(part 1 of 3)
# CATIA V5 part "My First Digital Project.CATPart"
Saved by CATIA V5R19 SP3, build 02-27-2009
Part number: My First Digital Project
Publications: "ElevationGridHeightReference", "Building Levels_ElevationOfRefHeight", "Level 1", "Roof Peak", "A", "B", "C", "D", "E", "F", "G", "H", "I", "1", "2", "3", "4", "5", "6", "7", "8", "9", "A-1", "A-2", "A-3", "A-4", "A-5", "A-6", "A-7", "A-8", "A-9", "B-1", "B-2", "B-3", "B-4", "B-5", "B-6", "B-7", "B-8", "B-9", "C-1", "C-2", "C-3", "C-4", "C-5", "C-6", "C-7", "C-8", "C-9", "D-1", "D-2", "D-3", "D-4", "D-5", "D-6", "D-7", "D-8", "D-9", "E-1", "E-2", "E-3", "E-4", "E-5", "E-6", "E-7", "E-8", "E-9", "F-1", "F-2", "F-3", "F-4", "F-5", "F-6", "F-7", "F-8", "F-9", "G-1", "G-2", "G-3", "G-4", "G-5", "G-6", "G-7", "G-8", "G-9", "H-1", "H-2", "H-3", "H-4", "H-5", "H-6", "H-7", "H-8", "H-9", "I-1", "I-2", "I-3", "I-4", "I-5", "I-6", "I-7", "I-8", "I-9"
Material "Brushed metal 2": density 7860 kg/m3, Young's modulus 2e+11 Pa, Poisson ratio 0.266
Material "Brushed metal 2": density 7860 kg/m3, Young's modulus 2e+11 Pa, Poisson ratio 0.266
Material "Brushed metal 2": density 7860 kg/m3, Young's modulus 2e+11 Pa, Poisson ratio 0.266
Material "Brushed metal 2": density 7860 kg/m3, Young's modulus 2e+11 Pa, Poisson ratio 0.266
Material "Brushed metal 2": density 7860 kg/m3, Young's modulus 2e+11 Pa, Poisson ratio 0.266
Material "Brushed metal 2": density 7860 kg/m3, Young's modulus 2e+11 Pa, Poisson ratio 0.266
Material "Brushed metal 2": density 7860 kg/m3, Young's modulus 2e+11 Pa, Poisson ratio 0.266
Material "Brushed metal 2": density 7860 kg/m3, Young's modulus 2e+11 Pa, Poisson ratio 0.266
Material "Brushed metal 2": density 7860 kg/m3, Young's modulus 2e+11 Pa, Poisson ratio 0.266
Material "Brushed metal 2": density 7860 kg/m3, Young's modulus 2e+11 Pa, Poisson ratio 0.266
Material "Brushed metal 2": density 7860 kg/m3, Young's modulus 2e+11 Pa, Poisson ratio 0.266
Material "Brushed metal 2": density 7860 kg/m3, Young's modulus 2e+11 Pa, Poisson ratio 0.266
Material "Brushed metal 2": density 7860 kg/m3, Young's modulus 2e+11 Pa, Poisson ratio 0.266
Material "Brushed metal 2": density 7860 kg/m3, Young's modulus 2e+11 Pa, Poisson ratio 0.266
Material "Brushed metal 2": density 7860 kg/m3, Young's modulus 2e+11 Pa, Poisson ratio 0.266
Material "Brushed metal 2": density 7860 kg/m3, Young's modulus 2e+11 Pa, Poisson ratio 0.266
Material "Brushed metal 2": density 7860 kg/m3, Young's modulus 2e+11 Pa, Poisson ratio 0.266
Material "Brushed metal 2": density 7860 kg/m3, Young's modulus 2e+11 Pa, Poisson ratio 0.266
Material "Wall of Castle": density 2770 kg/m3, Young's modulus 6e+10 Pa, Poisson ratio 0.27, thermal expansion 7e-06 1/K
Material "Wall of Castle": density 2770 kg/m3, Young's modulus 6e+10 Pa, Poisson ratio 0.27, thermal expansion 7e-06 1/K
Material "Wall of Castle": density 2770 kg/m3, Young's modulus 6e+10 Pa, Poisson ratio 0.27, thermal expansion 7e-06 1/K
Material "Wall of Castle": density 2770 kg/m3, Young's modulus 6e+10 Pa, Poisson ratio 0.27, thermal expansion 7e-06 1/K
Material "Wall of Castle": density 2770 kg/m3, Young's modulus 6e+10 Pa, Poisson ratio 0.27, thermal expansion 7e-06 1/K
Material "Wall of Castle": density 2770 kg/m3, Young's modulus 6e+10 Pa, Poisson ratio 0.27, thermal expansion 7e-06 1/K
Material "Wall of Castle": density 2770 kg/m3, Young's modulus 6e+10 Pa, Poisson ratio 0.27, thermal expansion 7e-06 1/K
Material "Wall of Castle": density 2770 kg/m3, Young's modulus 6e+10 Pa, Poisson ratio 0.27, thermal expansion 7e-06 1/K
Material "Wall of Castle": density 2770 kg/m3, Young's modulus 6e+10 Pa, Poisson ratio 0.27, thermal expansion 7e-06 1/K
Material "Wall of Castle": density 2770 kg/m3, Young's modulus 6e+10 Pa, Poisson ratio 0.27, thermal expansion 7e-06 1/K
Material "Concrete": density 2320 kg/m3, Young's modulus 2.5e+10 Pa, Poisson ratio 0.3, thermal expansion 1e-05 1/K
Material "Steel": density 7860 kg/m3, Young's modulus 2e+11 Pa, Poisson ratio 0.266, thermal expansion 1.17e-05 1/K
Material "Steel": density 7860 kg/m3, Young's modulus 2e+11 Pa, Poisson ratio 0.266, thermal expansion 1.17e-05 1/K
Material "Steel": density 7860 kg/m3, Young's modulus 2e+11 Pa, Poisson ratio 0.266, thermal expansion 1.17e-05 1/K
Material "Steel": density 7860 kg/m3, Young's modulus 2e+11 Pa, Poisson ratio 0.266, thermal expansion 1.17e-05 1/K
Material "Steel": density 7860 kg/m3, Young's modulus 2e+11 Pa, Poisson ratio 0.266, thermal expansion 1.17e-05 1/K
Material "Steel": density 7860 kg/m3, Young's modulus 2e+11 Pa, Poisson ratio 0.266, thermal expansion 1.17e-05 1/K
Material "Steel": density 7860 kg/m3, Young's modulus 2e+11 Pa, Poisson ratio 0.266, thermal expansion 1.17e-05 1/K
Material "Steel": density 7860 kg/m3, Young's modulus 2e+11 Pa, Poisson ratio 0.266, thermal expansion 1.17e-05 1/K
Material "Ox B&W Stripes": density 2000 kg/m3
Bounding box of the stored display mesh (mm): x -2751.913 to 38639.977, y -3048 to 24319.59, z -304.8 to 7419.866
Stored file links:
  D:\Work\2009-03-18 GT Knowledge SVN\GT.KNOWLEDGE\Training\Work\2009-T02.GettingStarted\Models\My First Digital Project.CATPart
  D:\Work\2009-03-18 GT Knowledge SVN\GT.KNOWLEDGE\Training\Work\2009-T02.GettingStarted\Models\Starter Sketches.CATPart
  C:\Program Files\Gehry Technologies\Digital Project V1,R4\Project Standards\startup\Catalogs\LayerSets\Standard Wall Layer Sets Imperial\ResolvedParts\CMU_8___-Partition.CATPart
  C:\Program Files\Gehry Technologies\Digital Project V1,R4\Project Standards\startup\Catalogs\Doors\IFC\IFC Single Swing - Lining - Glass.CATPart
  C:\Program Files\Gehry Technologies\Digital Project V1,R4\Project Standards\startup\Catalogs\Windows\IFC\Single Panel - Symbolic.CATPart
  C:\Program Files\Gehry Technologies\Digital Project V1,R4\Project Standards\startup\Catalogs\Windows\IFC\IFC Single Panel.CATPart
  C:\Program Files\Gehry Technologies\Digital Project V1,R4\Project Standards\startup\Catalogs\Windows\IFC\IFC Triple Panel Vertical.CATPart
  C:\Program Files\Gehry Technologies\Digital Project V1,R4\Project Standards\startup\Catalogs\LayerSets\Standard Wall Layer Sets Imperial\ResolvedParts\CMU_12__-Structure_with_Surface.CATPart
  D:\Work\2009-03-18 GT Knowledge SVN\GT.KNOWLEDGE\Training\Work\2009-T02.GettingStarted\Models\My First Drawing Sheet Redux.CATDrawing
  D:\Work\2009-03-18 GT Knowledge SVN\GT.KNOWLEDGE\Training\Work\2009-T02.GettingStarted\Models\My First Drawing Sheet.CATDrawing
  C:\Program Files\Gehry Technologies\Digital Project V1,R4\Project Standards\startup\materials\Catalog.CATMaterial
  C:\Program Files\Gehry Technologies\Digital Project V1,R4\Project Standards\startup\materials\brushed_metal1.jpg
  C:\Program Files\Gehry Technologies\Digital Project V1,R4\Project Standards\startup\materials\brushed_metal2.jpg
  C:\Program Files\Gehry Technologies\Digital Project V1,R4\Project Standards\startup\materials\wall_of_castle.jpg
  C:\Program Files\Gehry Technologies\Digital Project V1,R4\Project Standards\startup\materials\concrete.jpg
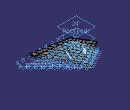
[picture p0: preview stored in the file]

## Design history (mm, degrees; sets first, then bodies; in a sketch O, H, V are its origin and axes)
GTCArcElevationGrid1 "Building Levels": ElevationOfRefHeight 0
GTCArcSlab1 "Slab"
GTCArcSlab2 "Slab"
GTCArcColumn1 "Column"
GTCArcColumn2 "Column"
GTCArcColumn3 "Column"
GTCArcColumn4 "Column"
GTCArcColumn5 "Column"
GTCArcColumn6 "Column"
GTCArcColumn7 "Column"
GTCArcColumn8 "Column"
GTCArcWall1 "Wall"
GTCArcWall2 "Wall"
GTCArcWall3 "Wall"
GTCArcWall4 "Wall"
GTCArcWall5 "Wall"
GTCArcWall6 "Wall"
GTCArcWall7 "Wall"
GTCArcWall8 "Wall"
GTCArcWall9 "Wall"
GTCArcWall10 "Wall"
GTCArcBeam1 "Beam"
GTCArcBeam2 "Beam"
GTCArcBeam3 "Beam"
GTCArcBeam4 "Beam"
GTCArcBeam5 "Beam"
GTCArcBeam6 "Beam"
GTCArcBeam7 "Beam"
GTCArcBeam8 "Beam"
GTCArcBeam9 "Beam"
GTCArcBeam10 "Beam"
GTCArcBeam11 "Beam"
GTCArcBeam12 "Beam"
GTCArcBeam13 "Beam"
GTCArcBeam14 "Beam"
GTCArcBeam15 "Beam"
GTCArcBeam16 "Beam"
GTCArcBeam17 "Beam"
GTCArcBeam18 "Beam"
GTCArcSectionCatalogRoot1 "Section Catalogs"
GTCArcPlanGrid1 "Grid East-West"
GTCArcPlanGrid2 "Grid North-South"
GTCArcIntersectionGrid1 "Grid Points"
GTCArcSheets1 "A&S Sheets"
Set1
  AxisSystem1: origin (0, 0, 0), X (1, 0, 0), Y (0, 1, 0), Z (0, 0, 1)
  Sketch1 on xy-plane, origin (0, 0, 0), H (1, 0, 0), V (0, 1, 0)
    point P1 (0, 14720.7096)
    line L1 (0, 14720.7096) -> (13368.4042, 22038.0431)
    line L2 (13368.4042, 22038.0431) -> (34424.4022, 0)
    line L3 (34424.4022, 0) -> (3944.4022, 0)
    line L4 (3944.4022, 0) -> (0, 14720.7096)
    point P3 (34424.4022, 0)
    construction line L5 (34424.4022, 0) -> (0, 14720.7096)
    angle L4 V = 15
    length L3 = 30480
    length L4 = 15240
    coincidence: P1 V, P3 H
    horizontal: L3 H
    symmetry: L3 L2 L5, L4 L1 L5
  Plane1: type Offset, RefPlane xy-plane, Offset 7315.2
  Line1: type PtDir, RefPoint sketch element, Direction xy-plane, Start 0, End 2438.4
  Line2: type PtDir, RefPoint sketch element, Direction xy-plane, Start 0, End 5486.4
  Line3: type PtDir, RefPoint sketch element, Direction xy-plane, Start 0, End 2438.4
  Line4: type PtDir, RefPoint sketch element, Direction xy-plane, Start 0, End 2438.4
  LineCorner1: Elements (vertex of Line1; vertex of Line2; vertex of Line3; vertex of Line4)
  Fill1: Boundary LineCorner1
  Sketch2 "Partitions" on xy-plane, origin (0, 0, 0), H (1, 0, 0), V (0, 1, 0)
    projected line E1 (34424.4022, 0) -> (3944.4022, 0) from sketch element
    projected line E2 (0, 14720.7096) -> (3944.4022, 0) from sketch element
    projected line E3 (0, 14720.7096) -> (13368.4042, 22038.0431) from sketch element
    projected line E4 (34424.4022, 0) -> (13368.4042, 22038.0431) from sketch element
    construction line L1 (0, 14720.7096) -> (34424.4022, 0)
    line L2 (8325.3671, 1828.8) -> (4962.35, 3266.9077)
    point P9 (4962.35, 3266.9077)
    line L3 (4962.35, 3266.9077) -> (4880.5472, 8987.1813)
    point P10 (4880.5472, 8987.1813)
    line L4 (4880.5472, 8987.1813) -> (7517.078, 15152.7126)
    point P11 (7517.078, 15152.7126)
    line L5 (7517.078, 15152.7126) -> (11709.5345, 19045.2091)
    point P12 (11709.5345, 19045.2091)
    line L6 (11709.5345, 19045.2091) -> (15072.5516, 17607.1014)
    point P13 (8325.3671, 1828.8)
    point P14 (15072.5516, 17607.1014)
    point P15 (6198.8126, 12069.9469)
    point P16 (13968.8059, 8084.3115)
    point P17 (13390.1652, 7011.1742)
    point P18 (12719.1739, 5993.2256)
    point P19 (11964.8857, 5035.3645)
    point P20 (14448.1752, 9205.3172)
    point P21 (14824.3558, 10365.0312)
    point P22 (15096.8362, 11553.3927)
    point P23 (15268.3289, 12760.4714)
    line L7 (2138.3258, 13806.3096) -> (5347.6898, 1828.8)
    line L8 (5347.6898, 1828.8) -> (30147.7506, 1828.8)
    line L9 (30147.7506, 1828.8) -> (13015.5317, 19760.0601)
    line L10 (13015.5317, 19760.0601) -> (2138.3258, 13806.3096)
    spline S1 through (8325.3671, 1828.8) (14221.2222, 8639.3699) (15072.5516, 17607.1014)
    construction line L11 (15072.5516, 17607.1014) -> (8325.3671, 1828.8)
    construction line L12 (11709.5345, 19045.2091) -> (4962.35, 3266.9077)
    construction spline S2 through (11709.5345, 19045.2091) (5813.6795, 12234.6392) (4962.35, 3266.9077)
    construction line L13 (13391.0431, 18326.1553) -> (6643.8586, 2547.8539)
    point P28 (13391.0431, 18326.1553)
    point P29 (6643.8586, 2547.8539)
    point P30 (8325.3671, 1828.8)
    point P31 (14221.2222, 8639.3699)
    point P32 (15072.5516, 17607.1014)
    point P33 (11709.5345, 19045.2091)
    point P34 (5813.6795, 12234.6392)
    point P35 (4962.35, 3266.9077)
    length L4 = 6705.6
    distance L1 P16 = 609.6
    distance P16 P17 = 1219.2
    distance P17 P18 = 1219.2
    distance P18 P19 = 1219.2
    length L6 = 3657.6
    distance P31 L11 = 2743.2
    distance L12 P34 = 2743.2
    distance L8 E1 = 1828.8
    distance L7 E2 = 1828.8
    parallelism: L6 L1
    midpoint: P15 L4, P28 L6, P29 L2
    coincidence: P16 S1, P17 S1, P18 S1, P19 S1, L8 P13, L7 P9, P12 L10, L9 P14, P30 P13, P31 L1, P32 P14, P33 P12, P34 L1, P35 P9, P15 L1, P11 S2, P10 S2
    symmetry: P16 P20 L1, P17 P21 L1, P18 P22 L1, P19 P23 L1, L2 L6 L1, L7 L10 L1, L8 L9 L1
  Sketch3 "Grid" on xy-plane, origin (0, 0, 0), H (1, 0, 0), V (0, 1, 0)
    projected line E1 (34424.4022, 0) -> (3944.4022, 0) from sketch element
    projected line E2 (34424.4022, 0) -> (13368.4042, 22038.0431) from sketch element
    point P3 (34424.4022, 0)
    projected line E3 (0, 14720.7096) -> (13368.4042, 22038.0431) from sketch element
    point P5 (0, 14720.7096)
    point P6 (13368.4042, 22038.0431)
    projected line E4 (0, 14720.7096) -> (3944.4022, 0) from sketch element
    point P7 (0, 14720.7096)
    point P8 (3944.4022, 0)
    point P9 (493.0503, 12880.6209)
    point P10 (986.1006, 11040.5322)
    point P11 (1479.1508, 9200.4435)
    point P12 (1972.2011, 7360.3548)
    point P13 (2465.2514, 5520.2661)
    point P14 (2958.3017, 3680.1774)
    point P15 (3451.352, 1840.0887)
    point P16 (31792.4025, 2754.7554)
    point P17 (29160.4027, 5509.5108)
    point P18 (26528.403, 8264.2662)
    point P19 (23896.4032, 11019.0216)
    point P20 (21264.4034, 13773.777)
    point P21 (18632.4037, 16528.5323)
    point P22 (16000.4039, 19283.2877)
    point P23 (23896.4032, 11019.0216)
    construction line L1 (34424.4022, 0) -> (0, 14720.7096)
    offset line E5 (36628.2066, 2105.5998) -> (15572.2085, 24143.6429) from sketch element
    offset line E6 (38639.978, 0) -> (15572.2085, 24143.6429) from sketch element
    line L2 (35881.8776, 2886.7373) -> (322.8841, 1739.1219)
    point P26 (35881.8776, 2886.7373)
    line L3 (33112.3623, 5785.4219) -> (-139.2731, 3463.9162)
    point P27 (33112.3623, 5785.4219)
    line L4 (30329.8087, 8697.7529) -> (-596.7117, 5171.1004)
    point P28 (30329.8087, 8697.7529)
    line L5 (27532.2702, 11625.7677) -> (-1048.2612, 6856.3061)
    point P29 (27532.2702, 11625.7677)
    line L6 (24717.3924, 14571.9305) -> (-1492.3291, 8513.5901)
    point P30 (24717.3924, 14571.9305)
    line L7 (21882.3005, 17539.2502) -> (-1926.6918, 10134.6538)
    point P31 (21882.3005, 17539.2502)
    line L8 (19023.4469, 20531.4399) -> (-2348.1478, 11707.5487)
    point P32 (19023.4469, 20531.4399)
    point P33 (-2348.1478, 11707.5487)
    reference offset line E7 (-2944.1419, 13931.8291) -> (1000.2603, -788.8804) from sketch element
    point P36 (-2348.1478, 11707.5487)
    point P37 (-1926.6918, 10134.6538)
    point P38 (-1492.3291, 8513.5901)
    point P39 (-1048.2612, 6856.3061)
    point P40 (-596.7117, 5171.1004)
    point P41 (-139.2731, 3463.9162)
    point P42 (322.8841, 1739.1219)
    point P43 (556.4821, 18500.0302)
    point P44 (8940.3063, -3048)
    line L9 (8940.3063, -3048) -> (556.4821, 18500.0302)
    point P45 (1984.8844, 19281.8809)
    point P46 (13078.6928, -3048)
    line L10 (13078.6928, -3048) -> (1984.8844, 19281.8809)
    point P47 (3457.0305, 20087.6752)
    point P48 (17182.6826, -3048)
    line L11 (17182.6826, -3048) -> (3457.0305, 20087.6752)
    point P49 (4962.0694, 20911.4737)
    point P50 (21257.4111, -3048)
    line L12 (21257.4111, -3048) -> (4962.0694, 20911.4737)
    point P51 (6492.4652, 21749.1516)
    point P52 (25307.0398, -3048)
    line L13 (25307.0398, -3048) -> (6492.4652, 21749.1516)
    point P53 (8042.8203, 22597.7544)
    point P54 (29334.9768, -3048)
    line L14 (29334.9768, -3048) -> (8042.8203, 22597.7544)
    point P55 (9609.1679, 23455.1109)
    point P56 (33344.0399, -3048)
    line L15 (33344.0399, -3048) -> (9609.1679, 23455.1109)
    line L16 (38639.978, 0) -> (788.8804, 0)
    point P57 (38639.978, 0)
    point P58 (788.8804, 0)
    line L17 (16136.4022, 23553.1353) -> (-2751.9132, 13214.4216)
    point P59 (-2751.9132, 13214.4216)
    point P60 (16136.4022, 23553.1353)
    point P61 (-811.9632, 17750.9976)
    point P62 (4761.1114, -3048)
    line L18 (4761.1114, -3048) -> (-811.9632, 17750.9976)
    point P63 (11188.5268, 24319.5892)
    point P64 (37336.5792, -3048)
    line L19 (37336.5792, -3048) -> (11188.5268, 24319.5892)
    distance P7 P9 = 1905 {= Sketch3.length(E4) /8}
    distance P9 P10 = 1905 {= Sketch3.distance(P7 P9)}
    distance P10 P11 = 1905 {= Sketch3.distance(P7 P9)}
    distance P11 P12 = 1905 {= Sketch3.distance(P7 P9)}
    distance P12 P13 = 1905 {= Sketch3.distance(P7 P9)}
    distance P13 P14 = 1905 {= Sketch3.distance(P7 P9)}
    distance P14 P15 = 1905 {= Sketch3.distance(P7 P9)}
    distance P3 P16 = 3810 {= Sketch3.length(E2) /8}
    distance P16 P17 = 3810 {= Sketch3.distance(P3 P16)}
    distance P17 P18 = 3810 {= Sketch3.distance(P3 P16)}
    distance P18 P19 = 3810 {= Sketch3.distance(P3 P16)}
    distance P19 P20 = 3810 {= Sketch3.distance(P3 P16)}
    distance P20 P21 = 3810 {= Sketch3.distance(P3 P16)}
    distance P21 P22 = 3810 {= Sketch3.distance(P3 P16)}
    length E4 = 15240 (reference)
    length E2 = 30480 (reference)
    coincidence: E4 P9, E4 P10, E4 P11, E4 P12, E4 P13, E4 P14, E4 P15, E2 P16, E2 P17, E2 P18, E2 P19, E2 P20, E2 P21, E2 P22, P23 E2, P26 E5, P15 L2, P16 L2, P27 E5, P14 L3, P17 L3, P28 E5, P18 L4, P13 L4, P29 E5, P30 E5, P31 E5, P32 E5, L8 P9, P19 L5, P12 L5, P20 L6, P11 L6, P21 L7, P10 L7, P22 L8, E7 P36, E7 P37, E7 P38, E7 P39, E7 P40, E7 P41, E7 P42, P3 L16, P8 L16, E7 P58, P6 L17, P5 L17, E7 P59, E5 P60
    symmetry: P36 P43 L1, P32 P44 L1, L8 L9 L1, P37 P45 L1, P31 P46 L1, L7 L10 L1, P38 P47 L1, P30 P48 L1, L6 L11 L1, P39 P49 L1, P29 P50 L1, L5 L12 L1, P40 P51 L1, P28 P52 L1, L4 L13 L1, P41 P53 L1, P27 P54 L1, L3 L14 L1, P42 P55 L1, P26 P56 L1, L2 L15 L1, P59 P61 L1, P60 P62 L1, L17 L18 L1, P58 P63 L1, P57 P64 L1, L16 L19 L1
    horizontal: L16 H
  Plane2: type 2Lines, Element1 {line type PtPt}, Element2 Z axis
Body1 (main body)
Body2 "Structural Solid Body", material "Ox B&W Stripes"
  GTCArcStrSlabSolidRes1 "Structural Solid": Perimeter 92819.0285, SurfaceArea 453.635, GrossVolume 23.0514
Body3 "Structural Solid Body", material "Concrete"
  GTCArcStrSlabSolidRes2 "Structural Solid": Perimeter 43729.3587, SurfaceArea 121.885, GrossVolume 37.1506
Set2 "Construction Geometry"
  Point1 "Construction Point 1": type OnCurve, Support sketch element
  Point2 "Construction Point 2": type OnCurve, Support sketch element
Set3 "Construction Geometry"
  Point3 "Construction Point 1": type OnCurve, Support sketch element
  Point4 "Construction Point 2": type OnCurve, Support sketch element
Set4 "Construction Geometry"
  Point5 "Construction Point 1": type OnCurve, Support sketch element
  Point6 "Construction Point 2": type OnCurve, Support sketch element
Set5 "Construction Geometry"
  Point7 "Construction Point 1": type OnCurve, Support sketch element
  Point8 "Construction Point 2": type OnCurve, Support sketch element
Set6 "Construction Geometry"
  Point9 "Construction Point 1": type OnCurve, Support sketch element
  Point10 "Construction Point 2": type OnCurve, Support sketch element
Set7 "Construction Geometry"
  Point11 "Construction Point 1": type OnCurve, Support sketch element
  Point12 "Construction Point 2": type OnCurve, Support sketch element
Body4 "Envelope Body", material "Wall of Castle"
  GTCArcWallEnvRes1 "Envelope": NominalLength 18040.4439, GrossFootPrintArea 3.66582, NetFootPrintArea 3.2528, GrossVolume 14.9783
Body5 "Envelope Body", material "Wall of Castle"
  GTCArcWallEnvRes2 "Envelope": NominalLength 3526.5012, GrossFootPrintArea 0.716585, NetFootPrintArea 0.716585, GrossVolume 2.39329
Body6 "Envelope Body", material "Wall of Castle"
  GTCArcWallEnvRes3 "Envelope": NominalLength 5772.1499, GrossFootPrintArea 1.1729, NetFootPrintArea 1.1729, GrossVolume 4.45137
Body7 "Envelope Body", material "Wall of Castle"
  GTCArcWallEnvRes4 "Envelope": NominalLength 6662.4603, GrossFootPrintArea 1.35381, NetFootPrintArea 1.35381, GrossVolume 5.80118
Body8 "Envelope Body", material "Wall of Castle"
  GTCArcWallEnvRes5 "Envelope": NominalLength 5494.3971, GrossFootPrintArea 1.11646, NetFootPrintArea 1.11646, GrossVolume 4.17586
Body9 "Envelope Body", material "Wall of Castle"
  GTCArcWallEnvRes6 "Envelope": NominalLength 3544.8468, GrossFootPrintArea 0.720313, NetFootPrintArea 0.720313, GrossVolume 2.4124
Body10 "Opening Volume Body"
  GTCArcGeoOpnVolume1 "Opening Volume"
Set8 "IFC Single Swing - Lining - Glass"
  Set9 "Construction Geometry"
    UdfFeature1 "Insertion Axis": UdfInputSpec1 {planeoffsetpt RefPlane Plane3}, UdfInputSpec2 Project1, UdfInputSpec3 Project2, UdfInputSpec4 {lineangle Support Plane4, Start 0, End 304.8, Angle 90}, UdfComponents Set12, UdfOutputs AxisSystem4
    AxisSystem2 "Insertion Axis Clone": origin (12134.1448, 5559.1105, 0), X (-0.6499, -0.76, 0), Y (0.76, -0.6499, 0), Z (0, 0, 1)
    AxisSystem3 "Panel Axis": origin (12257.6772, 5420.0475, 12.7), X (-0.6499, -0.76, 0), Y (0.76, -0.6499, 0), Z (0, 0, 1)
    UdfFeature2 "Middle": UdfInputSpec1 {pointcoord X 25.2984 {= `UdfFeature2.Inner Offset`}, Y 0, Z 0, RefAxis AxisSystem3}, UdfInputSpec2 {pointcoord X 482.6508 {= `UdfFeature2.Door Width` /2}, Y 0, Z 0, RefAxis AxisSystem3}, UdfInputSpec3 {pointcoord X 940.0032 {= `UdfFeature2.Door Width` -`UdfFeature2.Inner Offset`}, Y 0, Z 0, RefAxis AxisSystem3}, UdfComponents Set13, UdfOutputs Point14
  Set10 "Door Lining"
    Sketch4 "Opening Contour" on edge [XY plane of AxisSystem2 | ZX plane of AxisSystem2], origin (12134.1448, 5559.1105, 0), H (-0.6499, -0.76, 0), V (0, 0, 1)
      line L1 (0, 0) -> (0, 2476.5)
      line L2 (0, 2476.5) -> (1016.1016, 2476.5)
      line L3 (1016.1016, 2476.5) -> (1016.1016, 0)
      point P3 (1016.1016, 0)
      length L1 = 2476.5
      length L2 = 1016.1016
      vertical: L1 V, L3 V
      horizontal: L2 H
      coincidence: P3 H
    Body11 "Lining"
      Sketch5 on edge [XY plane of AxisSystem2 | ZX plane of AxisSystem2], origin (12134.1448, 5559.1105, 0), H (-0.6499, -0.76, 0), V (0.76, -0.6499, 0)
        point P1 (0, 203.315)
        line L1 (0, 203.315) -> (25.4, 203.315)
        line L2 (25.4, 203.315) -> (25.4, 0)
        line L3 (25.4, 0) -> (0, 0)
        line L4 (0, 0) -> (0, 203.315)
        distance H L1 = 203.315
        length L1 = 25.4
        length L4 = 203.315
        coincidence: P1 V
        horizontal: L1 H, L3 H
        vertical: L2 V, L4 V
      Rib1: profile Sketch5, centre curve Sketch4
    Body12 "Threshold"
      Sketch6 on edge [YZ plane of AxisSystem2 | XY plane of AxisSystem2], origin (12134.1448, 5559.1105, 0), H (0.76, -0.6499, 0), V (0, 0, 1)
        line L1 (0, 12.7) -> (203.315, 12.7)
        line L2 (203.315, 12.7) -> (203.315, 0)
        line L3 (203.315, 0) -> (0, 0)
        line L4 (0, 0) -> (0, 12.7)
        length L1 = 203.315
        distance L2 V = 203.315
        length L4 = 12.7
        horizontal: L1 H, L3 H
        vertical: L2 V, L4 V
        coincidence: H L3
      Pad1: profile Sketch6, direction (-0.6499, -0.76, 0), up to face of Rib1, opposite side up to face of Rib1
  Set11 "Door Panel"
    UdfFeature3 "Swinging": UdfInputSpec1 {pointcoord X -1000 {= UdfFeature3.Invert *1}, Y 0, Z 0, RefAxis AxisSystem3}, UdfInputSpec2 {lineptpt FirstPoint {point type Coord, X 25.4, Y 184.265, Z 12.7, RefAxis AxisSystem2}, SecondPoint Point16}, UdfInputSpec3 AxisSystem5, UdfInputSpec4 {pointcoord X 482.6508 {= UdfFeature3.SideOffset}, Y 0, Z 0, RefAxis AxisSystem3}, UdfComponents Set14, UdfOutputs Sketch7
    Body13 "Panel"
      UdfFeature4 "Swinging Glass Panel": UdfInputSpec1 {pointcoord X -1000 {= UdfFeature4.Invert *1}, Y 0, Z 0, RefAxis AxisSystem3}, UdfInputSpec2 {lineptpt FirstPoint {point type Coord, X 25.4, Y 184.265, Z 12.7, RefAxis AxisSystem2}, SecondPoint {point type Coord, X -1000 {= UdfFeature4.Invert *1}, Y 0, Z 0, RefAxis AxisSystem3}}, UdfInputSpec4 {pointcoord X 482.6508 {= UdfFeature4.SideOffset}, Y 0, Z 0, RefAxis AxisSystem3}, UdfInputSpec5 edge [ZX plane of AxisSystem3 | YZ plane of AxisSystem3], UdfComponents ({point type Coord, X -1000 {= UdfFeature4.Invert *1}, Y 0, Z 0, RefAxis AxisSystem3}; {line type PtPt, FirstPoint {point type Coord, X 25.4, Y 184.265, Z 12.7, RefAxis AxisSystem2}, SecondPoint {point type Coord, X -1000 {= UdfFeature4.Invert *1}, Y 0, Z 0, RefAxis AxisSystem3}}; {point type Coord, X -482.6508 {= -`UdfFeature4.Door Width` *UdfFeature4.PanelWidth /2}, Y 0, Z 0}; {line type Angle, RefPoint {point type Coord, X -482.6508 {= -`UdfFeature4.Door Width` *UdfFeature4.PanelWidth /2}, Y 0, Z 0}, Curve edge [XY plane of UdfFeature4 | ZX plane of UdfFeature4], Support XY plane of UdfFeature4, Start 0, End 304.8, Angle 0 {= `UdfFeature4.Open Ratio` *90deg}}; {line type PtDir, RefPoint {point type Coord, X -482.6508 {= -`UdfFeature4.Door Width` *UdfFeature4.PanelWidth /2}, Y 0, Z 0}, Direction edge [ZX plane of AxisSystem3 | YZ plane of AxisSystem3], Start 0, End 304.8}; a sketch; {join Elements (sketch element; sketch element)})
Set12 "Insertion Geometry"
  Plane3 "XY Plane - Equation": type Equation, A 0, B 0, C 1, Length 0
  Plane4 "Horizontal at Insertion Point": type OffsetPt, RefPlane Plane3
  Project1 "Insertion Point - Clone": Support Plane4
  Project2 "Insertion Line - Clone": Support Plane4
  Line5 "Hor - Normal to insertion Line": type Angle, Support Plane4, Start 0, End 304.8, Angle 90
  AxisSystem4 "Insertion Axis": origin (12134.1448, 5559.1105, 0), X (-0.6499, -0.76, 0), Y (0.76, -0.6499, 0), Z (0, 0, 1)
Set13 "UDF Geometry"
  Point13 "Left": (25.2984 {= `UdfFeature2.Inner Offset`}, 0, 0), in AxisSystem3
  Point14 "Middle": (482.6508 {= `UdfFeature2.Door Width` /2}, 0, 0), in AxisSystem3
  Point15 "Right": (940.0032 {= `UdfFeature2.Door Width` -`UdfFeature2.Inner Offset`}, 0, 0), in AxisSystem3
Set14 "UDF Geometry"
  Point16 "Invert Point": (-1000 {= UdfFeature3.Invert *1}, 0, 0), in AxisSystem3
  Line6 "Invert Line": type PtPt, FirstPoint {point type Coord, X 25.4, Y 184.265, Z 12.7, RefAxis AxisSystem2}, SecondPoint Point16
  AxisSystem5 "Panel Center Axis": origin (11943.9885, 5053.2352, 12.7), X (0.6499, 0.76, 0), Y (0.76, -0.6499, 0), Z (0, 0, 1)
  Sketch7 "Operation Symbol" on edge [XY plane of AxisSystem5 | ZX plane of AxisSystem5], origin (11943.9885, 5053.2352, 12.7), H (0.6499, 0.76, 0), V (0.76, -0.6499, 0)
    arc A1 centre (-482.6508, 0) radius 965.3016 from (482.6508, 0) to (-482.6508, 965.3016) ccw
    line L1 (-482.6508, 0) -> (482.6508, 0)
    line L2 (-482.6508, 965.3016) -> (-482.6508, 0)
    line L3 (-457.3524, 0) -> (-457.3524, 964.97)
    point P4 (-457.3524, 964.97)
    length L2 = 965.3016 {= `UdfFeature3.Door Width`*UdfFeature3.PanelWidth}
    distance L2 V = 482.6508 {= `UdfFeature3.Door Width` *UdfFeature3.PanelWidth /2}
    distance L2 L3 = 25.2984 {= UdfFeature3.PanelDepth}
    horizontal: L1 H
    coincidence: H L1, P4 A1
    vertical: L2 V, L3 V
Body14 "Opening Volume Body"
  GTCArcGeoOpnVolume2 "Opening Volume"
Set15 "IFC Single Swing - Lining - Glass"
  Set16 "Construction Geometry"
    UdfFeature5 "Insertion Axis": UdfInputSpec1 {planeoffsetpt RefPlane Plane5}, UdfInputSpec2 Project3, UdfInputSpec3 Project4, UdfInputSpec4 {lineangle Support Plane6, Start 0, End 304.8, Angle 90}, UdfComponents Set19, UdfOutputs AxisSystem8
    AxisSystem6 "Insertion Axis Clone": origin (15108.8885, 13287.2175, 0), X (-0.1005, -0.9949, 0), Y (0.9949, -0.1005, 0), Z (0, 0, 1)
    AxisSystem7 "Panel Axis": origin (15289.66, 13243.4242, 12.7), X (-0.1005, -0.9949, 0), Y (0.9949, -0.1005, 0), Z (0, 0, 1)
    UdfFeature6 "Middle": UdfInputSpec1 {pointcoord X 25.2984 {= `UdfFeature6.Inner Offset`}, Y 0, Z 0, RefAxis AxisSystem7}, UdfInputSpec2 {pointcoord X 482.6508 {= `UdfFeature6.Door Width` /2}, Y 0, Z 0, RefAxis AxisSystem7}, UdfInputSpec3 {pointcoord X 940.0032 {= `UdfFeature6.Door Width` -`UdfFeature6.Inner Offset`}, Y 0, Z 0, RefAxis AxisSystem7}, UdfComponents Set20, UdfOutputs Point18
  Set17 "Door Lining"
    Sketch8 "Opening Contour" on edge [XY plane of AxisSystem6 | ZX plane of AxisSystem6], origin (15108.8885, 13287.2175, 0), H (-0.1005, -0.9949, 0), V (0, 0, 1)
      line L1 (0, 0) -> (0, 2476.5)
      line L2 (0, 2476.5) -> (1016.1016, 2476.5)
      line L3 (1016.1016, 2476.5) -> (1016.1016, 0)
      point P3 (1016.1016, 0)
      length L1 = 2476.5
      length L2 = 1016.1016
      vertical: L1 V, L3 V
      horizontal: L2 H
      coincidence: P3 H
    Body15 "Lining"
      Sketch9 on edge [XY plane of AxisSystem6 | ZX plane of AxisSystem6], origin (15108.8885, 13287.2175, 0), H (-0.1005, -0.9949, 0), V (0.9949, -0.1005, 0)
        point P1 (0, 203.3081)
        line L1 (0, 203.3081) -> (25.4, 203.3081)
        line L2 (25.4, 203.3081) -> (25.4, 0)
        line L3 (25.4, 0) -> (0, 0)
        line L4 (0, 0) -> (0, 203.3081)
        distance H L1 = 203.3081
        length L1 = 25.4
        length L4 = 203.3081
        coincidence: P1 V
        horizontal: L1 H, L3 H
        vertical: L2 V, L4 V
      Rib2: profile Sketch9, centre curve Sketch8
    Body16 "Threshold"
      Sketch10 on edge [YZ plane of AxisSystem6 | XY plane of AxisSystem6], origin (15108.8885, 13287.2175, 0), H (0.9949, -0.1005, 0), V (0, 0, 1)
        line L1 (0, 12.7) -> (203.3081, 12.7)
        line L2 (203.3081, 12.7) -> (203.3081, 0)
        line L3 (203.3081, 0) -> (0, 0)
        line L4 (0, 0) -> (0, 12.7)
        length L1 = 203.3081
        distance L2 V = 203.3081
        length L4 = 12.7
        horizontal: L1 H, L3 H
        vertical: L2 V, L4 V
        coincidence: H L3
      Pad2: profile Sketch10, direction (-0.1005, -0.9949, 0), up to face of Rib2, opposite side up to face of Rib2
  Set18 "Door Panel"
    UdfFeature7 "Swinging": UdfInputSpec1 {pointcoord X 1000 {= UdfFeature7.Invert *1}, Y 0, Z 0, RefAxis AxisSystem7}, UdfInputSpec2 {lineptpt FirstPoint {point type Coord, X 25.4, Y 184.2581, Z 12.7, RefAxis AxisSystem6}, SecondPoint Point20}, UdfInputSpec3 AxisSystem9, UdfInputSpec4 {pointcoord X 482.6508 {= UdfFeature7.SideOffset}, Y 0, Z 0, RefAxis AxisSystem7}, UdfComponents Set21, UdfOutputs Sketch11
    Body17 "Panel"
      UdfFeature8 "Swinging Glass Panel": UdfInputSpec1 {pointcoord X 1000 {= UdfFeature8.Invert *1}, Y 0, Z 0, RefAxis AxisSystem7}, UdfInputSpec2 {lineptpt FirstPoint {point type Coord, X 25.4, Y 184.2581, Z 12.7, RefAxis AxisSystem6}, SecondPoint {point type Coord, X 1000 {= UdfFeature8.Invert *1}, Y 0, Z 0, RefAxis AxisSystem7}}, UdfInputSpec4 {pointcoord X 482.6508 {= UdfFeature8.SideOffset}, Y 0, Z 0, RefAxis AxisSystem7}, UdfInputSpec5 edge [ZX plane of AxisSystem7 | YZ plane of AxisSystem7], UdfComponents ({point type Coord, X 1000 {= UdfFeature8.Invert *1}, Y 0, Z 0, RefAxis AxisSystem7}; {line type PtPt, FirstPoint {point type Coord, X 25.4, Y 184.2581, Z 12.7, RefAxis AxisSystem6}, SecondPoint {point type Coord, X 1000 {= UdfFeature8.Invert *1}, Y 0, Z 0, RefAxis AxisSystem7}}; {point type Coord, X -482.6508 {= -`UdfFeature8.Door Width` *UdfFeature8.PanelWidth /2}, Y 0, Z 0}; {line type Angle, RefPoint {point type Coord, X -482.6508 {= -`UdfFeature8.Door Width` *UdfFeature8.PanelWidth /2}, Y 0, Z 0}, Curve edge [XY plane of UdfFeature8 | ZX plane of UdfFeature8], Support XY plane of UdfFeature8, Start 0, End 304.8, Angle 0 {= `UdfFeature8.Open Ratio` *90deg}}; {line type PtDir, RefPoint {point type Coord, X -482.6508 {= -`UdfFeature8.Door Width` *UdfFeature8.PanelWidth /2}, Y 0, Z 0}, Direction edge [ZX plane of AxisSystem7 | YZ plane of AxisSystem7], Start 0, End 304.8}; a sketch; {join Elements (sketch element; sketch element)})
Set19 "Insertion Geometry"
  Plane5 "XY Plane - Equation": type Equation, A 0, B 0, C 1, Length 0
  Plane6 "Horizontal at Insertion Point": type OffsetPt, RefPlane Plane5
  Project3 "Insertion Point - Clone": Support Plane6
  Project4 "Insertion Line - Clone": Support Plane6
  Line7 "Hor - Normal to insertion Line": type Angle, Support Plane6, Start 0, End 304.8, Angle 90
  AxisSystem8 "Insertion Axis": origin (15108.8885, 13287.2175, 0), X (-0.1005, -0.9949, 0), Y (0.9949, -0.1005, 0), Z (0, 0, 1)
Set20 "UDF Geometry"
  Point17 "Left": (25.2984 {= `UdfFeature6.Inner Offset`}, 0, 0), in AxisSystem7
  Point18 "Middle": (482.6508 {= `UdfFeature6.Door Width` /2}, 0, 0), in AxisSystem7
  Point19 "Right": (940.0032 {= `UdfFeature6.Door Width` -`UdfFeature6.Inner Offset`}, 0, 0), in AxisSystem7
Set21 "UDF Geometry"
  Point20 "Invert Point": (1000 {= UdfFeature7.Invert *1}, 0, 0), in AxisSystem7
  Line8 "Invert Line": type PtPt, FirstPoint {point type Coord, X 25.4, Y 184.2581, Z 12.7, RefAxis AxisSystem6}, SecondPoint Point20
  AxisSystem9 "Panel Center Axis": origin (15241.1431, 12763.2181, 12.7), X (-0.1005, -0.9949, 0), Y (0.9949, -0.1005, 0), Z (0, 0, 1)
  Sketch11 "Operation Symbol" on edge [XY plane of AxisSystem9 | ZX plane of AxisSystem9], origin (15241.1431, 12763.2181, 12.7), H (-0.1005, -0.9949, 0), V (0.9949, -0.1005, 0)
    arc A1 centre (-482.6508, 0) radius 965.3016 from (482.6508, 0) to (-482.6508, 965.3016) ccw
    line L1 (-482.6508, 0) -> (482.6508, 0)
    line L2 (-482.6508, 965.3016) -> (-482.6508, 0)
    line L3 (-457.3524, 0) -> (-457.3524, 964.97)
    point P4 (-457.3524, 964.97)
    length L2 = 965.3016 {= `UdfFeature7.Door Width`*UdfFeature7.PanelWidth}
    distance L2 V = 482.6508 {= `UdfFeature7.Door Width` *UdfFeature7.PanelWidth /2}
    distance L2 L3 = 25.2984 {= UdfFeature7.PanelDepth}
    horizontal: L1 H
    coincidence: H L1, P4 A1
    vertical: L2 V, L3 V
Body18 "Opening Volume Body"
  GTCArcGeoOpnVolume3 "Opening Volume"
Set22 "IFC Single Panel"
  Set23 "Construction Geometry"
    UdfFeature9 "Insertion Axis": UdfInputSpec1 {plane2lines}, UdfInputSpec3 Project5, UdfInputSpec4 Project6, UdfInputSpec5 Project7, UdfComponents Set26, UdfOutputs AxisSystem13
    AxisSystem10 "Insertion Axis Clone": origin (12402.7967, 5571.6519, 133.35), X (0.5857, 0.8105, 0), Y (-0.8105, 0.5857, 0), Z (0, 0, 1)
    AxisSystem11 "Lining Axis": origin (12371.9151, 5593.9663, 133.35), X (0.5857, 0.8105, 0), Y (-0.8105, 0.5857, 0), Z (0, 0, 1)
    AxisSystem12 "Panel Axis": origin (12408.807, 5590.8118, 152.4), X (0.5857, 0.8105, 0), Y (-0.8105, 0.5857, 0), Z (0, 0, 1)
    UdfFeature10 "Middle": UdfInputSpec1 {pointcoord X 0, Y 0, Z 0, RefAxis AxisSystem11}, UdfInputSpec2 {pointcoord X 526.9992 {= `UdfFeature10.Window Width` /2}, Y 0, Z 0, RefAxis AxisSystem11}, UdfInputSpec3 {pointcoord X 1053.9984 {= `UdfFeature10.Window Width`}, Y 0, Z 0, RefAxis AxisSystem11}, UdfComponents Set27, UdfOutputs Point22
  Set24 "Window Lining"
    Sketch12 "Opening Contour" on edge [XY plane of AxisSystem11 | ZX plane of AxisSystem11], origin (12371.9151, 5593.9663, 133.35), H (0.5857, 0.8105, 0), V (0, 0, 1)
      line L1 (0, 0) -> (1053.9984, 0)
      line L2 (1053.9984, 0) -> (1053.9984, 2324.1)
      line L3 (1053.9984, 2324.1) -> (0, 2324.1)
      line L4 (0, 2324.1) -> (0, 0)
      length L4 = 2324.1
      length L3 = 1053.9984
      horizontal: L1 H, L3 H
      vertical: L2 V, L4 V
    Body19 "Lining"
      Pad3: profile Sketch12, direction (0.8105, -0.5857, 0), length 38.1, mirrored extent, thin wall 19.05
  Set25 "Window Panel"
    Body20 "Panel"
      UdfFeature11 "IFC Window Panel": UdfInputSpec10 edge [ZX plane of AxisSystem12 | YZ plane of AxisSystem12], UdfInputSpec1 {pointcoord X 1015.8984 {= `External.Rotate Axis Offset`}, Y 0, Z 0, RefPoint vertex [YZ plane of AxisSystem12 | ZX plane of AxisSystem12 | XY plane of AxisSystem12], RefAxis AxisSystem12}, UdfInputSpec3 edge [ZX plane of AxisSystem12 | YZ plane of AxisSystem12], UdfInputSpec4 {pointcoord X 0, Y 0, Z 1015.8984 {= `External.Rotate Axis Offset`}, RefPoint vertex [YZ plane of AxisSystem12 | ZX plane of AxisSystem12 | XY plane of AxisSystem12], RefAxis AxisSystem12}, UdfComponents a sketch, UdfInputSpec6 edge [XY plane of AxisSystem12 | ZX plane of AxisSystem12], UdfInputSpec7 {pointcoord X 0 {= `External.X Translate`}, Y 0, Z 0 {= `External.Z Translate`}, RefPoint vertex [YZ plane of AxisSystem12 | ZX plane of AxisSystem12 | XY plane of AxisSystem12], RefAxis AxisSystem12}, UdfInputSpec9 edge [XY plane of AxisSystem12 | ZX plane of AxisSystem12], OperationType "SideHungRightHand", Open Ratio 0
Set26 "Insertion Geometry"
  Plane7 "Construction Plane": type 2Lines
  Project5 "Insertion Point clone": Support Plane7
  Project6 "Insertion Line Clone": Support Plane7
  Project7 "Orientation Line Clone": Support Plane7
  Line9 "X Direction": type Normal, RefPoint Project5, RefSkin Plane7, Start 0, End 1
  AxisSystem13 "Insertion Axis": origin (12402.7967, 5571.6519, 133.35), X (0.5857, 0.8105, 0), Y (-0.8105, 0.5857, 0), Z (0, 0, 1)
Set27 "UDF Geometry"
  Point21 "Left": (0, 0, 0), in AxisSystem11
  Point22 "Middle": (526.9992 {= `UdfFeature10.Window Width` /2}, 0, 0), in AxisSystem11
  Point23 "Right": (1053.9984 {= `UdfFeature10.Window Width`}, 0, 0), in AxisSystem11
Set28 "UDF Geometry"
  Line10 "V Rotation Axis": type PtDir, RefPoint {point type Coord, X 1015.8984 {= `External.Rotate Axis Offset`}, Y 0, Z 0, RefPoint vertex [YZ plane of AxisSystem12 | ZX plane of AxisSystem12 | XY plane of AxisSystem12], RefAxis AxisSystem12}, Direction edge [ZX plane of AxisSystem12 | YZ plane of AxisSystem12], Start 0, End 304.8
  Line11 "H Rotation Axis": type PtDir, RefPoint {point type Coord, X 0, Y 0, Z 1015.8984 {= `External.Rotate Axis Offset`}, RefPoint vertex [YZ plane of AxisSystem12 | ZX plane of AxisSystem12 | XY plane of AxisSystem12], RefAxis AxisSystem12}, Direction edge [XY plane of AxisSystem12 | ZX plane of AxisSystem12], Start 0, End 304.8
  Point24 "Translate Point": (0 {= `External.X Translate`}, 0, 0 {= `External.Z Translate`}), relative to vertex [YZ plane of AxisSystem12 | ZX plane of AxisSystem12 | XY plane of AxisSystem12], in AxisSystem12
  Line12 "Trans X Axis": type PtDir, RefPoint Point24, Direction edge [XY plane of AxisSystem12 | ZX plane of AxisSystem12], Start 0, End 304.8
  Line13 "Trans ZAxis": type PtDir, RefPoint Point24, Direction edge [ZX plane of AxisSystem12 | YZ plane of AxisSystem12], Start 0, End 304.8
  Rotate1 "Rotate Horizontal Point": ToTransfor Point24, Axis Line11, Angle 0 {= `External.Open Angle`}
  Rotate2 "Rotate Horizontal Z Axis": ToTransfor Line13, Axis Line11, Angle 0 {= `External.Open Angle`}
  Rotate3 "Rotate Vertical Point": ToTransfor Point24, Axis Line10, Angle 0 {= `External.Open Angle`}
  Rotate4 "Rotate Vertical X Axis": ToTransfor Line12, Axis Line10, Angle 0 {= `External.Open Angle`}
  Line14 "X Direction": stored without definition
  Line15 "Z Direction": stored without definition
  Point25 "Origin": stored without definition
  Plane8: type Normal, Curve Line15, RefPoint Point25
  Line16 "Y Direction": type Angle, RefPoint Point25, Curve Line14, Support Plane8, Start 0, End 304.8, Angle 90
  AxisSystem14 "Window Open Axis": origin (12408.807, 5590.8118, 152.4), X (0.5857, 0.8105, 0), Y (-0.8105, 0.5857, 0), Z (0, 0, 1)
Set29 "UDF Geometry"
  Point26 "B-L": (25.4 {= UdfFeature11.FrameThickness}, 0, 25.4 {= UdfFeature11.FrameThickness}), relative to vertex [YZ plane of UdfFeature11 | ZX plane of UdfFeature11 | XY plane of UdfFeature11], in 
  Point27 "B": (507.9492 {= `UdfFeature11.Panel Width` /2}, 0, 25.4 {= UdfFeature11.FrameThickness}), relative to vertex [YZ plane of UdfFeature11 | ZX plane of UdfFeature11 | XY plane of UdfFeature11], in 
  Point28 "B-R": (990.4984 {= `UdfFeature11.Panel Width` -UdfFeature11.FrameThickness}, 0, 25.4 {= UdfFeature11.FrameThickness}), relative to vertex [YZ plane of UdfFeature11 | ZX plane of UdfFeature11 | XY plane of UdfFeature11], in 
  Point29 "R": (990.4984 {= Point28.X}, 0, 1143 {= `UdfFeature11.Panel Height` /2}), relative to vertex [YZ plane of UdfFeature11 | ZX plane of UdfFeature11 | XY plane of UdfFeature11], in 
  Point30 "T-R": (990.4984 {= Point28.X}, 0, 2260.6 {= `UdfFeature11.Panel Height` -UdfFeature11.FrameThickness}), relative to vertex [YZ plane of UdfFeature11 | ZX plane of UdfFeature11 | XY plane of UdfFeature11], in 
  Point31 "T": (507.9492 {= Point27.X}, 0, 2260.6 {= Point30.Z}), relative to vertex [YZ plane of UdfFeature11 | ZX plane of UdfFeature11 | XY plane of UdfFeature11], in 
  Point32 "T-L": (25.4 {= Point26.X}, 0, 2260.6 {= Point30.Z}), relative to vertex [YZ plane of UdfFeature11 | ZX plane of UdfFeature11 | XY plane of UdfFeature11], in 
  Point33 "L": (25.4 {= Point26.X}, 0, 1143 {= Point29.Z}), relative to vertex [YZ plane of UdfFeature11 | ZX plane of UdfFeature11 | XY plane of UdfFeature11], in 
  Point34 "C": (507.9492 {= `UdfFeature11.Panel Width` /2}, 0, 1143 {= `UdfFeature11.Panel Height` /2}), relative to vertex [YZ plane of UdfFeature11 | ZX plane of UdfFeature11 | XY plane of UdfFeature11], in 
  Point35 "B2": (0, 0, 76.2), relative to Point27, in 
  Point36 "T2": (0, 0, -76.2), relative to Point31, in 
  Point37 "L2": (76.2, 0, 0), relative to Point33, in 
  Point38 "R2": (-76.2, 0, 0), relative to Point29, in 
  Point39 "L3": (-253.9746 {= -`UdfFeature11.Panel Width` /4}, 0, 0), relative to Point34, in 
  Point40 "R3": (253.9746 {= -Point39.X}, 0, 0), relative to Point34, in 
  Point41 "T3": (0, 0, 571.5 {= `UdfFeature11.Panel Height` /4}), relative to Point34, in 
  Point42 "B3": (0, 0, -571.5 {= - Point41.Z}), relative to Point34, in 
  LineCorner2 "Left": Elements (Point32; Point29; Point26)
  LineCorner3 "Right": Elements (Point30; Point33; Point28)
  LineCorner4 "Top": Elements (Point32; Point27; Point30)
  LineCorner5 "Bottom": Elements (Point26; Point31; Point28)
  Join1 "Left and Bottom": Elements (LineCorner2; LineCorner5)
  Join2 "Right and Bottom": Elements (LineCorner3; LineCorner5)
  LineCorner6 "Pivot H Top": Elements (Point37; Point33; Point31; Point29; Point38)
  LineCorner7 "Pivot H Bottom": Elements (Point33; Point27; Point29)
  Join3 "Pivot H": Elements (LineCorner6; LineCorner7)
  LineCorner8 "Pivot V Left": Elements (Point36; Point31; Point33; Point27; Point35)
  LineCorner9 "Pivot V Right": Elements (Point31; Point29; Point27)
  Join4 "Pivot V": Elements (LineCorner8; LineCorner9)
  Line17 "Sliding H": type PtPt, FirstPoint Point39, SecondPoint Point40
  Line18 "Sliding V": type PtPt, FirstPoint Point41, SecondPoint Point42
  Point43: (25.4 {= UdfFeature11.FrameThickness}, 0, 0), relative to Point26, in 
  Point44: (-25.4 {= -UdfFeature11.FrameThickness}, 0, 25.4 {= UdfFeature11.FrameThickness}), relative to Point28, in 
  Point45: (25.4 {= UdfFeature11.FrameThickness}, 0, -25.4 {= -UdfFeature11.FrameThickness}), relative to Point32, in 
  Point46: (-25.4 {= -UdfFeature11.FrameThickness}, 0, 0), relative to Point30, in 
  Point47: (0, 0, -25.4 {= -UdfFeature11.FrameThickness}), relative to Point30, in 
  Point48: (0, 0, 25.4 {= UdfFeature11.FrameThickness}), relative to Point26, in 
  LineCorner10 "Removable-1": Elements (Point32; Point46; Point44; Point48)
  LineCorner11 "Removable-2": Elements (Point45; Point47; Point28; Point43)
  Line19 "Removable-3": type PtPt, FirstPoint Point47, SecondPoint Point43
  Join5 "Removable": Elements (LineCorner10; LineCorner11; Line19)
  LineCorner12 "Fixed": Elements (Point32; Point30; Point28; Point26)
  DatumCurve1 "OperationSymbol"
Body21 "Opening Volume Body"
  GTCArcGeoOpnVolume4 "Opening Volume"
Set30 "IFC Single Panel"
  Set31 "Construction Geometry"
    UdfFeature12 "Insertion Axis": UdfInputSpec1 {plane2lines}, UdfInputSpec3 Project8, UdfInputSpec4 Project9, UdfInputSpec5 Project10, UdfComponents Set34, UdfOutputs AxisSystem18
    AxisSystem15 "Insertion Axis Clone": origin (13110.991, 6564.0833, 133.35), X (0.5134, 0.8581, 0), Y (-0.8581, 0.5134, 0), Z (0, 0, 1)
    AxisSystem16 "Lining Axis": origin (13078.2963, 6583.6451, 133.35), X (0.5134, 0.8581, 0), Y (-0.8581, 0.5134, 0), Z (0, 0, 1)
    AxisSystem17 "Panel Axis": origin (13115.3228, 6583.691, 152.4), X (0.5134, 0.8581, 0), Y (-0.8581, 0.5134, 0), Z (0, 0, 1)
    UdfFeature13 "Middle": UdfInputSpec1 {pointcoord X 0, Y 0, Z 0, RefAxis AxisSystem16}, UdfInputSpec2 {pointcoord X 526.9992 {= `UdfFeature13.Window Width` /2}, Y 0, Z 0, RefAxis AxisSystem16}, UdfInputSpec3 {pointcoord X 1053.9984 {= `UdfFeature13.Window Width`}, Y 0, Z 0, RefAxis AxisSystem16}, UdfComponents Set35, UdfOutputs Point50
  Set32 "Window Lining"
    Sketch13 "Opening Contour" on edge [XY plane of AxisSystem16 | ZX plane of AxisSystem16], origin (13078.2963, 6583.6451, 133.35), H (0.5134, 0.8581, 0), V (0, 0, 1)
      line L1 (0, 0) -> (1053.9984, 0)
      line L2 (1053.9984, 0) -> (1053.9984, 2324.1)
      line L3 (1053.9984, 2324.1) -> (0, 2324.1)
      line L4 (0, 2324.1) -> (0, 0)
      length L4 = 2324.1
      length L3 = 1053.9984
      horizontal: L1 H, L3 H
      vertical: L2 V, L4 V
    Body22 "Lining"
      Pad4: profile Sketch13, direction (0.8581, -0.5134, 0), length 38.1, mirrored extent, thin wall 19.05
  Set33 "Window Panel"
    Body23 "Panel"
      UdfFeature14 "IFC Window Panel": UdfInputSpec10 edge [ZX plane of AxisSystem17 | YZ plane of AxisSystem17], UdfInputSpec1 {pointcoord X 1015.8984 {= `External.Rotate Axis Offset`}, Y 0, Z 0, RefPoint vertex [YZ plane of AxisSystem17 | ZX plane of AxisSystem17 | XY plane of AxisSystem17], RefAxis AxisSystem17}, UdfInputSpec3 edge [ZX plane of AxisSystem17 | YZ plane of AxisSystem17], UdfInputSpec4 {pointcoord X 0, Y 0, Z 1015.8984 {= `External.Rotate Axis Offset`}, RefPoint vertex [YZ plane of AxisSystem17 | ZX plane of AxisSystem17 | XY plane of AxisSystem17], RefAxis AxisSystem17}, UdfComponents a sketch, UdfInputSpec6 edge [XY plane of AxisSystem17 | ZX plane of AxisSystem17], UdfInputSpec7 {pointcoord X 0 {= `External.X Translate`}, Y 0, Z 0 {= `External.Z Translate`}, RefPoint vertex [YZ plane of AxisSystem17 | ZX plane of AxisSystem17 | XY plane of AxisSystem17], RefAxis AxisSystem17}, UdfInputSpec9 edge [XY plane of AxisSystem17 | ZX plane of AxisSystem17], OperationType "SideHungRightHand", Open Ratio 0
Set34 "Insertion Geometry"
  Plane9 "Construction Plane": type 2Lines
  Project8 "Insertion Point clone": Support Plane9
  Project9 "Insertion Line Clone": Support Plane9
  Project10 "Orientation Line Clone": Support Plane9
  Line20 "X Direction": type Normal, RefPoint Project8, RefSkin Plane9, Start 0, End 1
  AxisSystem18 "Insertion Axis": origin (13110.991, 6564.0833, 133.35), X (0.5134, 0.8581, 0), Y (-0.8581, 0.5134, 0), Z (0, 0, 1)
Set35 "UDF Geometry"
  Point49 "Left": (0, 0, 0), in AxisSystem16
  Point50 "Middle": (526.9992 {= `UdfFeature13.Window Width` /2}, 0, 0), in AxisSystem16
  Point51 "Right": (1053.9984 {= `UdfFeature13.Window Width`}, 0, 0), in AxisSystem16
Set36 "UDF Geometry"
  Line21 "V Rotation Axis": type PtDir, RefPoint {point type Coord, X 1015.8984 {= `External.Rotate Axis Offset`}, Y 0, Z 0, RefPoint vertex [YZ plane of AxisSystem17 | ZX plane of AxisSystem17 | XY plane of AxisSystem17], RefAxis AxisSystem17}, Direction edge [ZX plane of AxisSystem17 | YZ plane of AxisSystem17], Start 0, End 304.8
  Line22 "H Rotation Axis": type PtDir, RefPoint {point type Coord, X 0, Y 0, Z 1015.8984 {= `External.Rotate Axis Offset`}, RefPoint vertex [YZ plane of AxisSystem17 | ZX plane of AxisSystem17 | XY plane of AxisSystem17], RefAxis AxisSystem17}, Direction edge [XY plane of AxisSystem17 | ZX plane of AxisSystem17], Start 0, End 304.8
  Point52 "Translate Point": (0 {= `External.X Translate`}, 0, 0 {= `External.Z Translate`}), relative to vertex [YZ plane of AxisSystem17 | ZX plane of AxisSystem17 | XY plane of AxisSystem17], in AxisSystem17
  Line23 "Trans X Axis": type PtDir, RefPoint Point52, Direction edge [XY plane of AxisSystem17 | ZX plane of AxisSystem17], Start 0, End 304.8
  Line24 "Trans ZAxis": type PtDir, RefPoint Point52, Direction edge [ZX plane of AxisSystem17 | YZ plane of AxisSystem17], Start 0, End 304.8
  Rotate5 "Rotate Horizontal Point": ToTransfor Point52, Axis Line22, Angle 0 {= `External.Open Angle`}
  Rotate6 "Rotate Horizontal Z Axis": ToTransfor Line24, Axis Line22, Angle 0 {= `External.Open Angle`}
  Rotate7 "Rotate Vertical Point": ToTransfor Point52, Axis Line21, Angle 0 {= `External.Open Angle`}
  Rotate8 "Rotate Vertical X Axis": ToTransfor Line23, Axis Line21, Angle 0 {= `External.Open Angle`}
  Line25 "X Direction": stored without definition
  Line26 "Z Direction": stored without definition
  Point53 "Origin": stored without definition
  Plane10: type Normal, Curve Line26, RefPoint Point53
  Line27 "Y Direction": type Angle, RefPoint Point53, Curve Line25, Support Plane10, Start 0, End 304.8, Angle 90
  AxisSystem19 "Window Open Axis": origin (13115.3228, 6583.691, 152.4), X (0.5134, 0.8581, 0), Y (-0.8581, 0.5134, 0), Z (0, 0, 1)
